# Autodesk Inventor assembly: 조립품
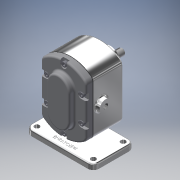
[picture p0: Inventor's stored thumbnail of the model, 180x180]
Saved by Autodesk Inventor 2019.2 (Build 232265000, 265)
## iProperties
Created: 2019-03
Part Number: 조립품
Material: 일반
Document SubType Name: Assembly
Designer: User
Author: User
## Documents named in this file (11)
- C:\Users\User\Desktop\490307V1035\조립품.iam
- C:\Users\User\Desktop\490307V1035\본체.ipt
- C:\Users\User\Desktop\490307V1035\메인축.ipt
- C:\Users\User\Desktop\490307V1035\서브축.ipt
- C:\Users\User\Desktop\490307V1035\키 6 x 6 x 18.ipt
- C:\Users\User\Desktop\490307V1035\베어링부시.ipt
- C:\Users\User\Desktop\490307V1035\스퍼기어.ipt
- C:\Users\User\Desktop\490307V1035\오일 실 16 28 7.ipt
- C:\Users\User\Desktop\490307V1035\커버.ipt
- C:\Users\User\Desktop\490307V1035\개스킷.ipt
- C:\Users\User\Desktop\490307V1035\볼트 M5.ipt
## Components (1 placed, 1 different names)
1. 개스킷:1
